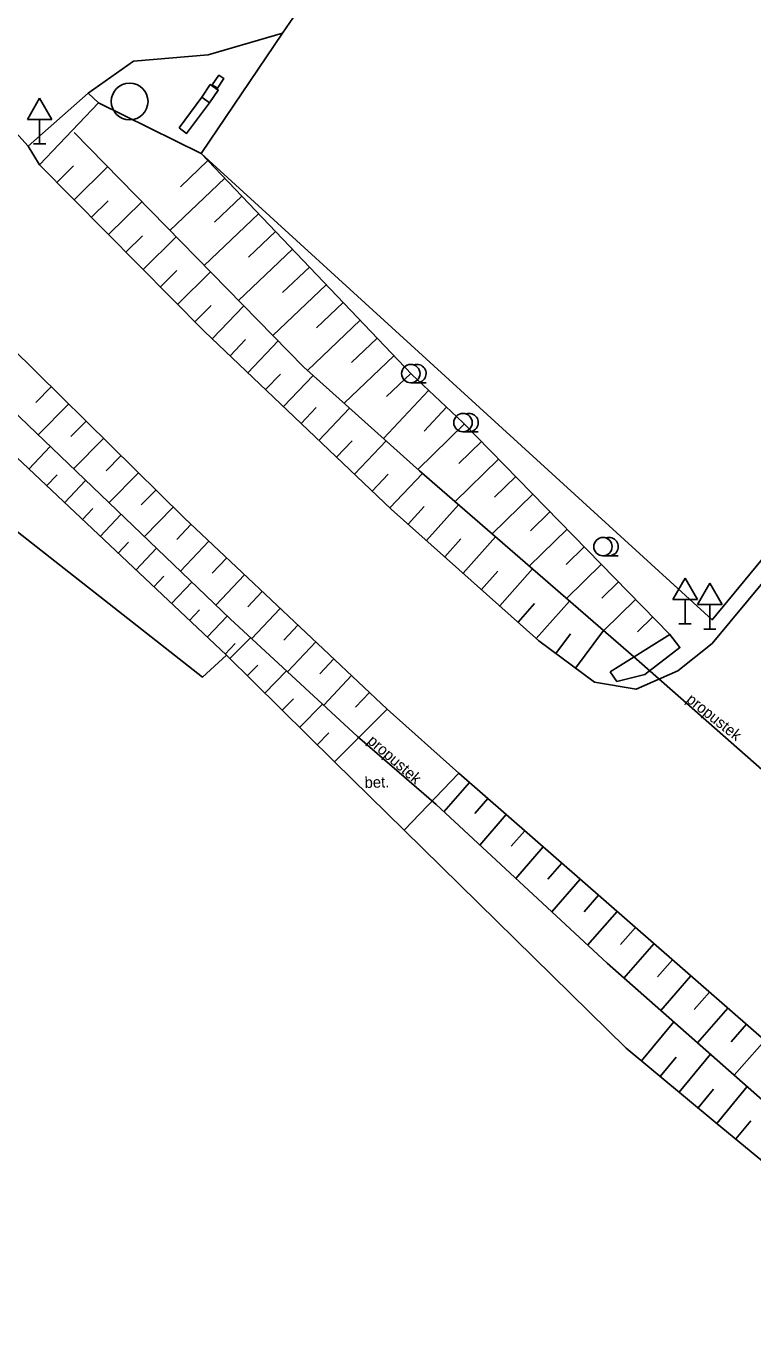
# Model space of a CAD drawing. Extents: x -747135 to -746147, y -1093269 to -1091735.
# Drawn here: x -746977.5 to -746947.9, y -1092274.5 to -1092220.8 of the extents above; entities that cross this region are included whole.
import ezdxf

# ---------------------------------------------------------------- set-up
doc = ezdxf.new("R2010")
doc.units = 0
for name, color, linetype in [('101', 7, 'Continuous'), ('1016', 7, 'Continuous'), ('1029', 7, 'Continuous'), ('105', 7, 'Continuous'), ('23700', 7, 'Continuous'), ('305', 7, 'Continuous'), ('306', 7, 'Continuous'), ('308', 7, 'Continuous'), ('316', 7, 'Continuous'), ('803', 7, 'Continuous')]:
    doc.layers.add(name, color=color, linetype=linetype)

msp = doc.modelspace()

# ---------------------------------------------------------------- linework, layer by layer
at = {"layer": '101'}
msp.add_line((-746974.54, -1092223.95), (-746970.35, -1092226.01), dxfattribs=at)
for points in [[(-746952.71, -1092246.53), (-746961.45, -1092238.96), (-746966.16, -1092234.73), (-746975.539, -1092225.162)], [(-746970.075, -1092226.299), (-746971.199, -1092227.37)], [(-746951.23, -1092245.63), (-746959.67, -1092236.99), (-746961.76, -1092235.03), (-746970.35, -1092226.01)], [(-746976.237, -1092227.191), (-746975.555, -1092226.516)], [(-746975.533, -1092227.902), (-746974.173, -1092226.555)], [(-746969.385, -1092227.023), (-746971.624, -1092229.156)], [(-746974.83, -1092228.612), (-746974.151, -1092227.941)], [(-746974.126, -1092229.323), (-746972.773, -1092227.984)], [(-746968.695, -1092227.747), (-746969.81, -1092228.809)], [(-746968.006, -1092228.472), (-746970.224, -1092230.584)], [(-746973.423, -1092230.034), (-746972.748, -1092229.366)], [(-746972.719, -1092230.745), (-746971.373, -1092229.412)], [(-746967.316, -1092229.196), (-746968.42, -1092230.247)], [(-746966.626, -1092229.92), (-746968.824, -1092232.013)], [(-746965.937, -1092230.644), (-746967.03, -1092231.685)], [(-746972.016, -1092231.455), (-746971.344, -1092230.791)], [(-746971.313, -1092232.166), (-746969.973, -1092230.84)], [(-746965.247, -1092231.368), (-746967.424, -1092233.441)], [(-746970.609, -1092232.877), (-746969.941, -1092232.216)], [(-746969.896, -1092233.578), (-746968.612, -1092232.228)], [(-746964.558, -1092232.092), (-746965.641, -1092233.124)], [(-746963.868, -1092232.817), (-746966.014, -1092234.861)], [(-746969.172, -1092234.267), (-746968.542, -1092233.605)], [(-746968.447, -1092234.957), (-746967.211, -1092233.658)], [(-746963.178, -1092233.541), (-746964.223, -1092234.536)], [(-746962.489, -1092234.265), (-746964.522, -1092236.201)], [(-746967.723, -1092235.646), (-746967.117, -1092235.009)], [(-746966.998, -1092236.335), (-746965.789, -1092235.064)], [(-746961.799, -1092234.989), (-746962.787, -1092235.93)], [(-746976.472, -1092235.529), (-746977.099, -1092236.164)], [(-746961.072, -1092235.675), (-746962.917, -1092237.643)], [(-746963.97, -1092249.79), (-746969.17, -1092245), (-746978.08, -1092236.46)], [(-746975.76, -1092236.232), (-746977.004, -1092237.492)], [(-746966.274, -1092237.025), (-746965.659, -1092236.378)], [(-746965.549, -1092237.714), (-746964.3, -1092236.401)], [(-746960.342, -1092236.359), (-746961.257, -1092237.335)], [(-746975.048, -1092236.934), (-746975.665, -1092237.559)], [(-746959.615, -1092237.046), (-746961.515, -1092238.902)], [(-746978.84, -1092237.52), (-746969.32, -1092246.48)], [(-746974.336, -1092237.637), (-746975.56, -1092238.876)], [(-746977.384, -1092238.891), (-746976.511, -1092237.964)], [(-746964.825, -1092238.403), (-746964.19, -1092237.736)], [(-746964.1, -1092239.092), (-746962.811, -1092237.737)], [(-746958.917, -1092237.761), (-746959.837, -1092238.66)], [(-746973.625, -1092238.339), (-746974.231, -1092238.953)], [(-746958.218, -1092238.477), (-746959.999, -1092240.217)], [(-746976.655, -1092239.576), (-746976.222, -1092239.116)], [(-746972.913, -1092239.041), (-746974.115, -1092240.26)], [(-746963.376, -1092239.782), (-746962.721, -1092239.094)], [(-746962.651, -1092240.471), (-746961.321, -1092239.072)], [(-746957.519, -1092239.192), (-746958.38, -1092240.033)], [(-746975.927, -1092240.261), (-746975.067, -1092239.348)], [(-746972.201, -1092239.744), (-746972.797, -1092240.348)], [(-746961.159, -1092241.803), (-746959.857, -1092240.34)], [(-746956.82, -1092239.907), (-746958.482, -1092241.531)], [(-746975.199, -1092240.947), (-746974.772, -1092240.493)], [(-746974.471, -1092241.632), (-746973.623, -1092240.732)], [(-746971.489, -1092240.446), (-746972.671, -1092241.644)], [(-746961.906, -1092241.138), (-746961.259, -1092240.412)], [(-746956.121, -1092240.623), (-746956.922, -1092241.405)], [(-746970.771, -1092241.142), (-746971.346, -1092241.753)], [(-746955.423, -1092241.338), (-746956.965, -1092242.845)], [(-746973.743, -1092242.318), (-746973.322, -1092241.871)], [(-746970.043, -1092241.827), (-746971.199, -1092243.056)], [(-746960.413, -1092242.468), (-746959.757, -1092241.731)], [(-746959.666, -1092243.133), (-746958.345, -1092241.65)], [(-746973.014, -1092243.003), (-746972.179, -1092242.116)], [(-746954.724, -1092242.053), (-746955.465, -1092242.777)], [(-746969.315, -1092242.513), (-746969.896, -1092243.13)], [(-746958.172, -1092244.463), (-746956.833, -1092242.959)], [(-746954.025, -1092242.769), (-746955.448, -1092244.159)], [(-746972.286, -1092243.688), (-746971.872, -1092243.248)], [(-746971.558, -1092244.374), (-746970.735, -1092243.5)], [(-746968.586, -1092243.198), (-746969.755, -1092244.44)], [(-746958.919, -1092243.798), (-746958.254, -1092243.051)], [(-746953.326, -1092243.484), (-746954.008, -1092244.15)], [(-746967.858, -1092243.883), (-746968.444, -1092244.506)], [(-746970.83, -1092245.059), (-746970.422, -1092244.625)], [(-746967.13, -1092244.568), (-746968.295, -1092245.806)], [(-746957.426, -1092245.128), (-746956.751, -1092244.371)], [(-746956.679, -1092245.793), (-746955.321, -1092244.269)], [(-746952.628, -1092244.199), (-746953.931, -1092245.473)], [(-746970.102, -1092245.744), (-746969.291, -1092244.884)], [(-746951.929, -1092244.915), (-746952.551, -1092245.522)], [(-746966.402, -1092245.254), (-746966.98, -1092245.869)], [(-746955.886, -1092246.402), (-746955.291, -1092245.606)], [(-746955.085, -1092247.001), (-746953.938, -1092245.467)], [(-746969.373, -1092246.43), (-746968.966, -1092245.997)], [(-746969.182, -1092246.617), (-746968.341, -1092245.764)], [(-746965.673, -1092245.939), (-746966.823, -1092247.162)], [(-746964.945, -1092246.624), (-746965.516, -1092247.232)], [(-746968.47, -1092247.319), (-746968.037, -1092246.88)], [(-746967.758, -1092248.021), (-746966.869, -1092247.12)], [(-746964.217, -1092247.309), (-746965.352, -1092248.517)], [(-746967.046, -1092248.723), (-746966.589, -1092248.26)], [(-746963.488, -1092247.995), (-746964.053, -1092248.594)], [(-746966.334, -1092249.426), (-746965.397, -1092248.476)], [(-746965.622, -1092250.128), (-746965.141, -1092249.641)], [(-746959.41, -1092251.666), (-746960.455, -1092252.862)], [(-746937.38, -1092272.89), (-746946.54, -1092265.43), (-746953.79, -1092259.04), (-746960.77, -1092252.57)], [(-746958.656, -1092252.323), (-746959.189, -1092252.933)], [(-746957.903, -1092252.981), (-746958.987, -1092254.223)], [(-746957.15, -1092253.639), (-746957.702, -1092254.271)], [(-746956.397, -1092254.297), (-746957.52, -1092255.583)], [(-746955.643, -1092254.954), (-746956.215, -1092255.609)], [(-746954.89, -1092255.612), (-746956.052, -1092256.943)], [(-746954.137, -1092256.27), (-746954.728, -1092256.946)], [(-746953.383, -1092256.927), (-746954.585, -1092258.303)], [(-746952.63, -1092257.585), (-746953.241, -1092258.284)], [(-746951.877, -1092258.243), (-746953.102, -1092259.646)], [(-746951.124, -1092258.9), (-746951.738, -1092259.604)], [(-746950.37, -1092259.558), (-746951.602, -1092260.969)], [(-746949.617, -1092260.216), (-746950.234, -1092260.923)], [(-746948.864, -1092260.874), (-746950.101, -1092262.291)], [(-746952.392, -1092263.022), (-746951.075, -1092261.433)], [(-746948.111, -1092261.531), (-746948.731, -1092262.242)], [(-746947.357, -1092262.189), (-746948.601, -1092263.613)], [(-746951.623, -1092263.661), (-746950.973, -1092262.878)], [(-746950.853, -1092264.299), (-746949.574, -1092262.756)], [(-746950.083, -1092264.937), (-746949.453, -1092264.177)], [(-746949.313, -1092265.575), (-746948.077, -1092264.075)], [(-746948.541, -1092266.211), (-746947.934, -1092265.474)]]:
    msp.add_lwpolyline(points, dxfattribs=at)
at = {"layer": '1016'}
for p, q in [((-746962.76, -1092248.68), (-746964.91, -1092250.83)), ((-746959.84, -1092251.29), (-746962.07, -1092253.62))]:
    msp.add_line(p, q, dxfattribs=at)
for points in [[(-746898.18, -1092134.6), (-746904.12, -1092139.99), (-746912.01, -1092144.83), (-746920.08, -1092149.17), (-746928.02, -1092152.73), (-746936.45, -1092155.39), (-746944.61, -1092157.47), (-746953.75, -1092158.71), (-746964.92, -1092159.66), (-746970.4, -1092160.58), (-746974.78, -1092162.27), (-746978.42, -1092164.61), (-746982.83, -1092169.13), (-746985.04, -1092172.77), (-746987.83, -1092179.63), (-746991.85, -1092191.24), (-746993.29, -1092198.31), (-746992.77, -1092203.42), (-746990.96, -1092208.81), (-746987.41, -1092214.26), (-746982.51, -1092220.09), (-746977.41, -1092225.71), (-746976.94, -1092226.48)], [(-746977.062, -1092234.946), (-746980.26, -1092231.79), (-746989.49, -1092221.72), (-746998.35, -1092211.08), (-747009.11, -1092197.43), (-747021.23, -1092181.39)], [(-746954.31, -1092247.58), (-746952.61, -1092247.87), (-746950.91, -1092247.12), (-746949.5, -1092246), (-746932.35, -1092225.35), (-746926.2, -1092217.84), (-746927.09, -1092214.99), (-746939.89, -1092204.98), (-746942.35, -1092203), (-746940.65, -1092200.7), (-746937.68, -1092201.89), (-746936.17, -1092200.22)], [(-746967.04, -1092221.11), (-746970.07, -1092221.99), (-746973.11, -1092222.25), (-746974.96, -1092223.55)], [(-746976.94, -1092226.48), (-746974.54, -1092223.95), (-746974.96, -1092223.55), (-746977.41, -1092225.71)], [(-746976.94, -1092226.48), (-746970.22, -1092233.27), (-746962.6, -1092240.52), (-746956.57, -1092245.89), (-746954.31, -1092247.58)], [(-746962.76, -1092248.68), (-746971.05, -1092240.88), (-746977.059, -1092234.949)], [(-746953.67, -1092247.15), (-746953.39, -1092247.55), (-746952.25, -1092247.27), (-746950.82, -1092246.17), (-746951.23, -1092245.63), (-746953.67, -1092247.15)], [(-746962.76, -1092248.68), (-746959.84, -1092251.29)], [(-746936.66, -1092271.22), (-746945.89, -1092263.47), (-746959.84, -1092251.29)]]:
    msp.add_lwpolyline(points, dxfattribs=at)
at = {"layer": '1029'}
for p, q in [((-746961.799, -1092235.364), (-746961.174, -1092235.364)), ((-746959.67, -1092237.365), (-746959.045, -1092237.365)), ((-746953.96, -1092242.425), (-746953.335, -1092242.425))]:
    msp.add_line(p, q, dxfattribs=at)
for centre in [(-746961.799, -1092234.989), (-746959.67, -1092236.99), (-746953.96, -1092242.05)]:
    msp.add_circle(centre, 0.375, dxfattribs=at)
for centre in [(-746961.549, -1092234.989), (-746959.42, -1092236.99), (-746953.71, -1092242.05)]:
    msp.add_arc(centre, 0.375, 249.4944, 109.0474, dxfattribs=at)
at = {"layer": '23700'}
for points in [[(-746952.71, -1092246.53), (-746946.57, -1092251.94)], [(-746963.97, -1092249.79), (-746960.77, -1092252.57)]]:
    msp.add_lwpolyline(points, dxfattribs=at)
at = {"layer": '305'}
msp.add_lwpolyline([(-746966.44, -1092220.24), (-746967.04, -1092221.11)], dxfattribs=at)
at = {"layer": '306'}
for p, q in [((-746976.94, -1092223.754), (-746977.44, -1092224.62)), ((-746976.94, -1092223.754), (-746976.44, -1092224.62)), ((-746977.44, -1092224.62), (-746976.44, -1092224.62)), ((-746976.94, -1092225.62), (-746976.94, -1092224.62)), ((-746977.19, -1092225.62), (-746976.69, -1092225.62)), ((-746950.61, -1092243.334), (-746951.11, -1092244.2)), ((-746950.61, -1092243.334), (-746950.11, -1092244.2)), ((-746949.6, -1092243.544), (-746950.1, -1092244.41)), ((-746949.6, -1092243.544), (-746949.1, -1092244.41)), ((-746951.11, -1092244.2), (-746950.11, -1092244.2)), ((-746950.61, -1092245.2), (-746950.61, -1092244.2)), ((-746950.1, -1092244.41), (-746949.1, -1092244.41)), ((-746949.6, -1092245.41), (-746949.6, -1092244.41)), ((-746950.86, -1092245.2), (-746950.36, -1092245.2)), ((-746949.85, -1092245.41), (-746949.35, -1092245.41))]:
    msp.add_line(p, q, dxfattribs=at)
at = {"layer": '308'}
for points in [[(-746964.91, -1092250.83), (-746969.32, -1092246.48), (-746970.3, -1092247.37), (-746979.38, -1092240.25)], [(-746964.91, -1092250.83), (-746962.07, -1092253.62)], [(-746953.01, -1092262.51), (-746962.07, -1092253.62)]]:
    msp.add_lwpolyline(points, dxfattribs=at)
at = {"layer": '316'}
for points in [[(-746969.9, -1092223.21), (-746969.63, -1092222.82), (-746969.422, -1092222.959), (-746969.681, -1092223.351), (-746969.9, -1092223.21)], [(-746971.25, -1092224.97), (-746970.33, -1092223.71), (-746970.01, -1092223.95), (-746970.948, -1092225.197), (-746971.25, -1092224.97)], [(-746970.33, -1092223.71), (-746969.98, -1092223.2), (-746969.652, -1092223.429), (-746970.01, -1092223.95), (-746970.33, -1092223.71)]]:
    msp.add_lwpolyline(points, dxfattribs=at)
msp.add_circle((-746973.27, -1092223.89), 0.75, dxfattribs=at)
at = {"layer": '803'}
for points in [[(-746967.04, -1092221.11), (-746970.35, -1092226.01), (-746949.5, -1092245.03), (-746932.73, -1092224.69)], [(-746938.51, -1092274.48), (-746949.38, -1092265.52), (-746953.01, -1092262.51)]]:
    msp.add_lwpolyline(points, dxfattribs=at)

# ---------------------------------------------------------------- texts
at = {"layer": '105'}
for s, rotation, p in [('propustek', 321.4591, (-746950.596, -1092248.354)), ('propustek', 318.9078, (-746963.603, -1092250.03)), ('bet.', 1.384, (-746963.678, -1092251.894))]:
    msp.add_text(s, height=0.45, rotation=rotation, dxfattribs=at).set_placement(p)

doc.saveas('drawing.dxf')
